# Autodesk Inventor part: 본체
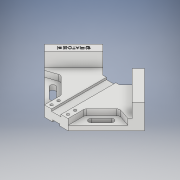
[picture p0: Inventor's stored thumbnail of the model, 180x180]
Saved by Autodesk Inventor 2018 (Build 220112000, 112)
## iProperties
Created: 2019-04
Part Number: 본체
Material: ABS Plastic
Document SubType Name: Modeling
Designer: Administrator
Density: 1.06 g/cm^3
Appearance: Smooth - White
Mass: 236.127 g
Surface Area: 426.592 cm^2
Volume: 222.762 cm^3
Author: Administrator
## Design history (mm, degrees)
sketch "Sketch2"
  geometry: L1 (84.853, -84.853)-(35.355, -134.35); L2 (-35.355, -134.35)-(-84.853, -84.853); L3 (-84.853, -84.853)-(-20, -20); L4 (20, -20)-(84.853, -84.853); L5 (84.853, -84.853)-(-84.853, -84.853); L6 (0, -169.706)-(0, 0); L7 (20, -20)-(-20, -20); L8 (35.355, -134.35)-(14.005, -113); L9 (14.005, -113)-(-14.005, -113); L10 (-14.005, -113)-(-35.355, -134.35); L11 (35.355, -134.35)-(84.853, -84.853); L12 (84.853, -84.853)-(74.246, -74.246); L13 (74.246, -74.246)-(24.749, -123.744); L14 (24.749, -123.744)-(35.355, -134.35); L15 (-35.355, -134.35)-(-84.853, -84.853); L16 (-84.853, -84.853)-(-74.246, -74.246); L17 (-74.246, -74.246)-(-24.749, -123.744); L18 (-24.749, -123.744)-(-35.355, -134.35); 2 further points
  constraints: 36 end point, 7 parallel, 5 perpendicular, 2 horizontal, 2 midpoint, 1 coincident, 1 collinear, 1 vertical, 2 other
  dimensions: "d25" = 40 distance of L4.start L3.end; "d26" = 20 distance from line of point (0, 0) L7; "d27" = 50 distance from line of L6.start L8; "d28" = 50 distance from line of L6.start L10; "d29" = 93 distance between parallel lines of L7 L9; "d30" = 120 distance from line of L3 L6.start; "d31" = 120 distance from line of point (0, 0) L1; "d34" = 15 distance between parallel lines of L1 L13; "d35" = 15 distance between parallel lines of L2 L17
extrude "Extrusion1" new body sketch "Sketch2" distance "d32" = 18; taper "d33" = 0 deg
extrude "Extrusion2" join sketch "Sketch2" distance "d36" = 42; taper "d37" = 0 deg
sketch "Sketch3"
  geometry: L1 (-20, 20)-(-84.853, 84.853) reference; L2 (-70.711, 70.711)-(-52.429, 76.805); L3 (-47.312, 75.597)-(-21.464, 49.749); L4 (-20, 46.213)-(-20, 20); L5 (-70.711, 70.711)-(-20, 20); L6 (20, 20)-(-20, 20) reference; L7 (0, 20)-(0, 113); L8 (-14.005, 113)-(14.005, 113) reference; L9 (-84.853, 84.853)-(-35.355, 134.35) reference; L10 (20, 46.213)-(20, 20); L11 (20, 20)-(70.711, 70.711); L12 (47.312, 75.597)-(21.464, 49.749); L13 (70.711, 70.711)-(52.429, 76.805); A1 r 5 centre (-50.848, 72.061) between (-47.312, 75.597) and (-52.429, 76.805); A2 r 5 centre (-25, 46.213) between (-20, 46.213) and (-21.464, 49.749); A3 r 5 centre (25, 46.213) between (21.464, 49.749) and (20, 46.213); A4 r 5 centre (50.848, 72.061) between (52.429, 76.805) and (47.312, 75.597); 6 further points
  constraints: 18 end point, 11 point on line, 8 point on circle, 8 tangent, 6 symmetric about line, 4 centre point, 3 equal radius, 2 midpoint, 1 collinear, 1 vertical
  dimensions: "d38" = 20 distance from line of L2.start L9; "d39" = 30 distance from line of point (-49.497, 77.782) L9; "d41" = 20 distance from line of L1 point (-49.497, 77.782); "d42" = 40 diameter of L4.end L7; "d49" = 20 distance from line of L5 point (-20, 48.284); "d50" = 5 radius of A1 (derived)
extrude "Extrusion3" cut sketch "Sketch3" distance "d51" = 10; taper "d52" = 0 deg
sketch "Sketch4"
  geometry: L1 (49.497, 63.64)-(32.527, 46.669); L2 (46.315, 66.822)-(29.345, 49.851); L3 (35.709, 43.487)-(52.679, 60.458); L4 (20, 20)-(-20, 20) reference; L5 (0, 20)-(0, 113); L6 (-14.005, 113)-(14.005, 113) reference; L7 (84.853, 84.853)-(20, 20) reference; L8 (35.355, 134.35)-(84.853, 84.853) reference; L9 (-35.709, 43.487)-(-52.679, 60.458); L10 (-46.315, 66.822)-(-29.345, 49.851); L11 (-49.497, 63.64)-(-32.527, 46.669); A1 r 4.5 centre (49.497, 63.64) between (52.679, 60.458) and (46.315, 66.822); A2 r 4.5 centre (32.527, 46.669) between (29.345, 49.851) and (35.709, 43.487); A3 r 4.5 centre (-49.497, 63.64) between (-46.315, 66.822) and (-52.679, 60.458); A4 r 4.5 centre (-32.527, 46.669) between (-35.709, 43.487) and (-29.345, 49.851); 2 further points
  constraints: 16 end point, 8 point on circle, 6 symmetric about line, 4 centre point, 4 tangent, 3 midpoint, 2 parallel, 1 coincident, 2 other
  dimensions: "d54" = 9 distance between parallel lines of L3 L2; "d55" = 10 distance from line of L7 point (41.012, 55.154); "d57" = 40 distance from line of L1.start L8; "d59" = 24 distance of L11.start L11.end
extrude "Extrusion4" cut sketch "Sketch4" distance "d60" = 8; taper "d61" = 0 deg
sketch "Sketch5"
  geometry: L1 (-8, 113)-(8, 113); L2 (8, 113)-(8, 20); L3 (8, 20)-(-8, 20); L4 (-8, 20)-(-8, 113); L5 (-14.005, 113)-(14.005, 113) reference; L6 (20, 20)-(-20, 20) reference; 3 further points
  constraints: 8 end point, 4 midpoint, 2 parallel, 1 horizontal, 1 perpendicular
  dimensions: "d62" = 16 distance between parallel lines of L2 L4
extrude "Extrusion5" cut sketch "Sketch5" distance "d63" = 3.5; taper "d64" = 0 deg
sketch "Sketch6"
  geometry: L1 (-6, -20)-(6, -20); L2 (6, -20)-(6, -113); L3 (6, -113)-(-6, -113); L4 (-6, -113)-(-6, -20); L5 (8, -20)-(-8, -20) reference; L6 (-8, -113)-(8, -113) reference; 3 further points
  constraints: 8 end point, 4 midpoint, 2 parallel, 1 horizontal, 1 perpendicular
  dimensions: "d65" = 12 distance between parallel lines of L2 L4
extrude "Extrusion6" cut sketch "Sketch6" distance "d66" = 3; taper "d67" = 0 deg
sketch "Sketch7"
  geometry: L1 (8, 20)-(-8, 20) reference; L2 (0, 20)-(-14, 20); L3 (-14, 20)-(-14, 26); L4 (-14, 26)-(-14, 38); L5 (0, 20)-(0, 35.802); L6 (14, 26)-(14, 38); L7 (14, 20)-(14, 26); L8 (0, 20)-(14, 20); C1 r 2.25 at (-14, 38); C2 r 2.25 at (-14, 26); C3 r 2.25 at (14, 38); C4 r 2.25 at (14, 26); C5 r 4 at (-14, 38); C6 r 4 at (-14, 26); C7 r 4 at (14, 26); C8 r 4 at (14, 38); 1 further point
  constraints: 14 end point, 8 centre point, 8 coincident, 3 symmetric about line, 2 point on line, 1 collinear, 1 midpoint, 1 perpendicular, 1 vertical
  dimensions: "d68" = 14 distance of L2.start L2.end; "d69" = 6 distance of L2.end L3.end; "d70" = 12 distance of L3.end L4.end; "d71" = 4.5 diameter of C1; "d72" = 4.5 diameter of C3; "d73" = 4.5 diameter of C4; "d74" = 4.5 diameter of C2; "d75" = 8 diameter of C5; "d76" = 8 diameter of C6; "d77" = 8 diameter of C7; "d78" = 8 diameter of C8
extrude "Extrusion7" cut sketch "Sketch7" distance "d79" = 8; taper "d80" = 0 deg
sketch "Sketch9"
  geometry: C1 r 2.25 at (0, 0) reference; C2 r 4 at (0, 0); C3 r 2.25 at (0, 12) reference; C4 r 4 at (0, 12); C5 r 2.25 at (28, 12) reference; C6 r 4 at (28, 12); C7 r 2.25 at (28, 0) reference; C8 r 4 at (28, 0); 1 further point
  constraints: 4 centre point, 4 coincident
  dimensions: "d81" = 8 diameter of C2; "d82" = 8 diameter of C4; "d83" = 8 diameter of C6; "d84" = 8 diameter of C8
extrude "Extrusion8" cut sketch "Sketch9" distance "d85" = 80; taper "d86" = 0 deg
sketch "Sketch10"
  geometry: L1 (-35.355, 134.35)-(-14.005, 113) reference; L2 (-35.355, 134.35)-(-30.052, 129.047); L3 (-30.052, 129.047)-(-54.801, 104.298); 2 further points
  constraints: 4 end point, 1 coincident, 1 perpendicular, 1 point on line, 1 other
  dimensions: "d87" = 7.5 distance of L1.start L2.end; "d88" = 35 distance of L2.end L3.end
emboss "Emboss1" sketch "Sketch10" dims "d25" = 40, "d26" = 20, "d27" = 50, "d28" = 50, "d29" = 93, "d30" = 120, "d31" = 120, "d34" = 15, "d35" = 15, "d89" = 0.5, "d90" = 0
body "Solid1"
